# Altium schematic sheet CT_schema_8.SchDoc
size 252 x 159 mm
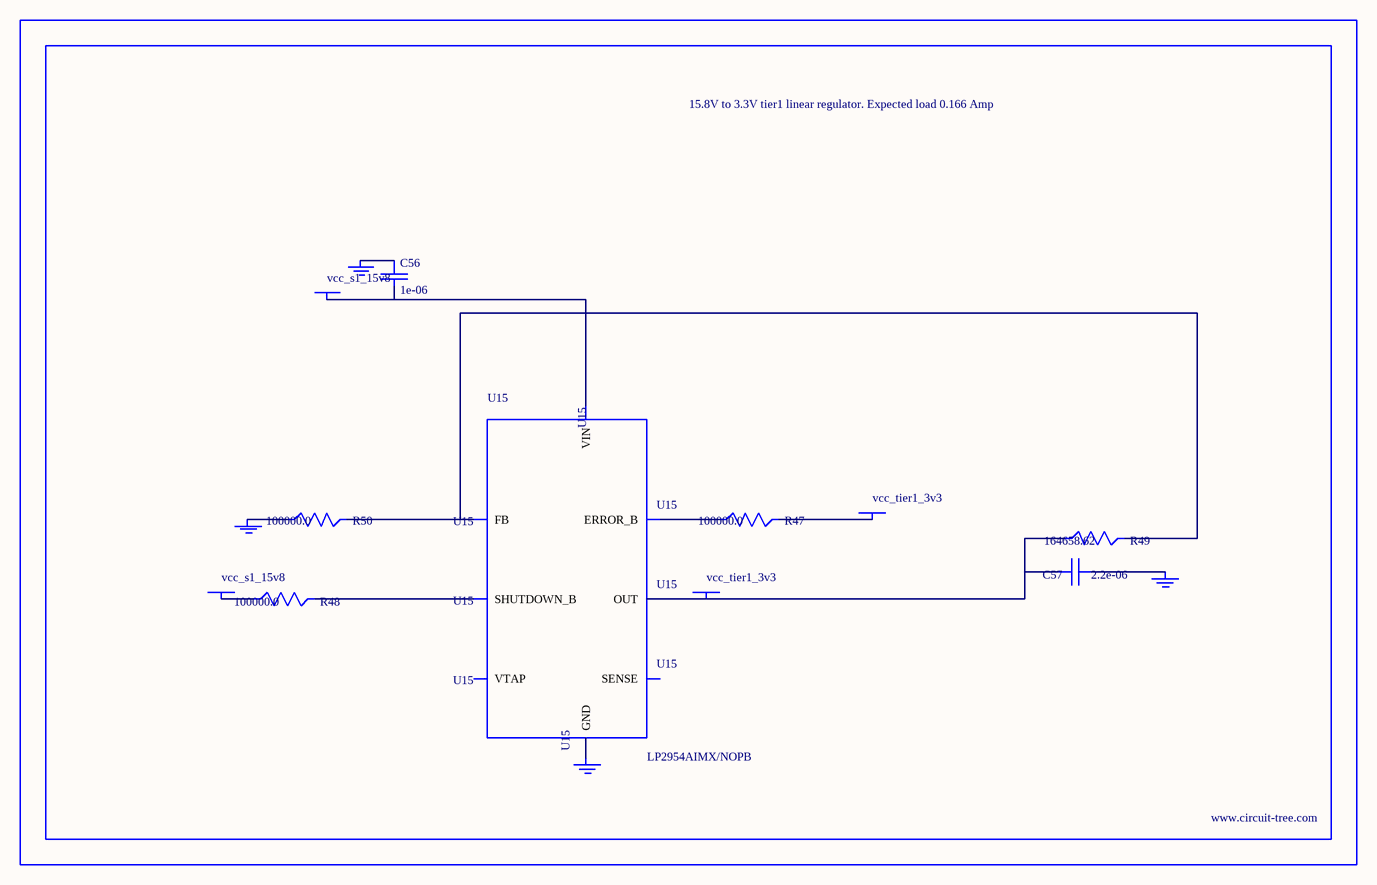
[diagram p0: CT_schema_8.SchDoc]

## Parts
BORDER7  (no value)
C56  1e-06  [EXV-9B]
C57  2.2e-06  [EXV-9B]
GND_INSTANCE_7_0  (no value)
GND_INSTANCE_7_1  (no value)
GND_INSTANCE_7_2  (no value)
GND_INSTANCE_7_3  (no value)
POWER_INSTANCE_7_0  vcc_s1_15v8
POWER_INSTANCE_7_1  vcc_tier1_3v3
POWER_INSTANCE_7_2  vcc_s1_15v8
POWER_INSTANCE_7_3  vcc_tier1_3v3
R47  100000.0  [R0603]
R48  100000.0  [R0603]
R49  164658.62  [R0603]
R50  100000.0  [R0603]
U15  LP2954AIMX/NOPB  [LP2954]

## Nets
NetC56_1: C56.1 GND_INSTANCE_7_2.0(GND)
NetC56_2: C56.2 POWER_INSTANCE_7_2.0(PWR) U15.8(VIN)
NetC57_1: C57.1 GND_INSTANCE_7_0.0(GND)
NetC57_2: C57.2 POWER_INSTANCE_7_3.0(PWR) R49.1 U15.1(OUT)
NetGND_INSTANCE_7_1_0: GND_INSTANCE_7_1.0(GND) R50.1
NetGND_INSTANCE_7_3_0: GND_INSTANCE_7_3.0(GND) U15.4(GND)
NetPOWER_INSTANCE_7_0_0: POWER_INSTANCE_7_0.0(PWR) R48.1
NetPOWER_INSTANCE_7_1_0: POWER_INSTANCE_7_1.0(PWR) R47.2
NetR47_1: R47.1 U15.5(ERROR_B)
NetR48_2: R48.2 U15.3(SHUTDOWN_B)
NetR49_2: R49.2 R50.2 U15.7(FB)

Not connected (* = marked no-connect by the designer): U15 2(SENSE) 6(VTAP)

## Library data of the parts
BORDER7 = BORDER_PAGE7
C56 = EDK105M050A9BAA
C57 = EDK225M050A9BAA
GND_INSTANCE_7_0-GND_INSTANCE_7_3 = GND
POWER_INSTANCE_7_0-POWER_INSTANCE_7_3 = PWR
R47 R48 R50 = RC0603JR-07100KL
R49 = R49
